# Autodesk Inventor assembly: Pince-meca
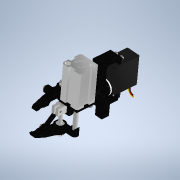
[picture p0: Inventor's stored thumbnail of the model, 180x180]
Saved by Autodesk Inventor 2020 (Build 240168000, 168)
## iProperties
Created: 2023-10
Part Number: Pince-meca
Document SubType Name: Assembly
Designer: bruno
Mass: 175.607 g
Surface Area: 502.561 cm^2
Volume: 102.899 cm^3
Density: 1.7066 g/cm^3
Author: bruno
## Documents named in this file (7)
- C:\Users\bruno\Documents\1-Cours-2023-24\Maquettes-Inventor\Pince-robot-Dobot\Pince-meca.iam
- C:\Users\bruno\Documents\1-Cours-2023-24\Maquettes-Inventor\Pince-robot-Dobot\Servo.iam
- C:\Users\bruno\Documents\1-Cours-2023-24\Maquettes-Inventor\Pince-robot-Dobot\pince-dr.iam
- C:\Users\bruno\Documents\1-Cours-2023-24\Maquettes-Inventor\Pince-robot-Dobot\Coulisseau.iam
- C:\Users\bruno\Documents\1-Cours-2023-24\Maquettes-Inventor\Pince-robot-Dobot\pince-ga.iam
- C:\Users\bruno\Documents\1-Cours-2023-24\Maquettes-Inventor\Pince-robot-Dobot\Axe-vertical.iam
- C:\Users\bruno\Documents\1-Cours-2023-24\Maquettes-Inventor\Pince-robot-Dobot\Bielle.iam
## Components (7 placed, 6 different names)
1. Servo:1 [sub-assembly] — Placage:1, Placage:2, Angle:1
2. pince-dr:1 [sub-assembly] — Placage:3, Placage:7, Placage:9
3. Coulisseau:1 [sub-assembly] — Placage:4, Placage:8, Placage:12
4. pince-ga:1 [sub-assembly] — Placage:5, Placage:10, Placage:11, Angle:1
5. Axe-vertical:1 [sub-assembly] — Placage:1, Placage:2, Placage:3, Placage:4, Placage:5
6. Bielle:1 [sub-assembly] — Placage:7, Placage:8, Placage:9
7. Bielle:2 [sub-assembly] — Placage:10, Placage:11, Placage:12
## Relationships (12: Mate 11, Angle 1)
- Placage:1 [Mate]: Servo:1 ↔ Axe-vertical:1
- Placage:2 [Mate]: Servo:1 ↔ Axe-vertical:1
- Placage:3 [Mate]: pince-dr:1 ↔ Axe-vertical:1
- Placage:4 [Mate]: Coulisseau:1 ↔ Axe-vertical:1
- Placage:5 [Mate]: pince-ga:1 ↔ Axe-vertical:1
- Placage:7 [Mate]: pince-dr:1 ↔ Bielle:1
- Placage:8 [Mate]: Coulisseau:1 ↔ Bielle:1
- Placage:9 [Mate]: pince-dr:1 ↔ Bielle:1
- Placage:10 [Mate]: pince-ga:1 ↔ Bielle:2
- Placage:11 [Mate]: pince-ga:1 ↔ Bielle:2
- Placage:12 [Mate]: Coulisseau:1 ↔ Bielle:2
- Angle:1: Servo:1 ↔ pince-ga:1
